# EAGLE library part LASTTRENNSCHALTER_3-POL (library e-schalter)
Lasttrennschalter, 3-pol.
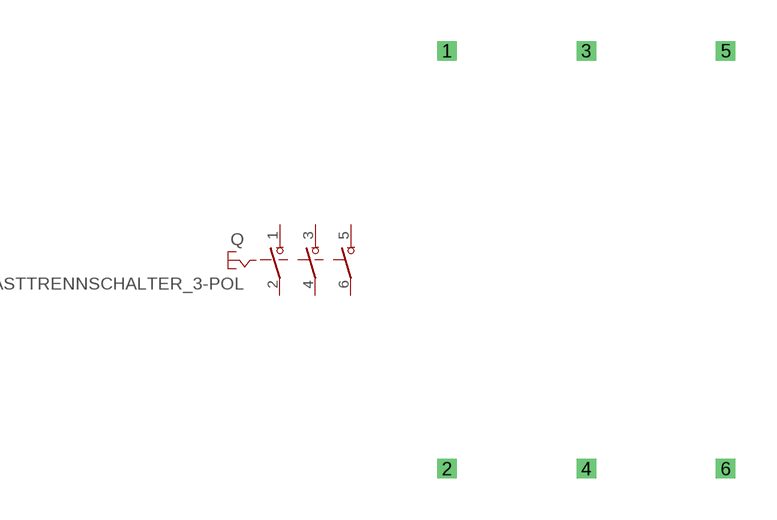
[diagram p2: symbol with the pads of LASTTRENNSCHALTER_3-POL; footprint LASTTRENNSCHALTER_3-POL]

Designator prefix Q

## LASTTRENNSCHALTER_3-POL  [LASTTRENNSCHALTER_3-POL]
1  1  in
2  2  in
3  3  in
4  4  in
5  5  in
6  6  in

## Footprint LASTTRENNSCHALTER_3-POL (pad centres in mm)
Dummy
drill 0.2 pad 0.6 square: 1 0,7.62; 2 0,-7.62; 3 5.08,7.62; 4 5.08,-7.62; 5 10.16,7.62; 6 10.16,-7.62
